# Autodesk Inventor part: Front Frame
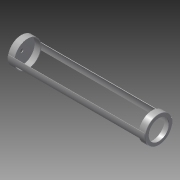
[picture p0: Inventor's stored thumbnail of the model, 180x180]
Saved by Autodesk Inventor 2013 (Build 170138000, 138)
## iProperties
Created: 2009-03
Part Number: Front Frame
Document SubType Name: Modeling
Designer: tangg
Density: 7.86 g/cm^3
Material: Steel, Mild
Mass: 173.384 g
Surface Area: 347.527 cm^2
Volume: 22.059 cm^3
Author: tangg
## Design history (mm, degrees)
sketch "Sketch1"
  geometry: L1 (-14.427, -29.5)-(-1, -29.5); L2 (0, -28.5)-(0, 0); L3 (0, 0)-(-1.5, 0); L4 (-14.427, -28)-(-14.427, -29.5); L5 (-14.427, -28)-(-1.5, -28); L6 (-1.5, -28)-(-1.5, 0); L7 (-1.5, 0)-(-17.075, 0); L8 (-150, -53.823)-(-150, 38.657); L9 (-285.573, -29.5)-(-299, -29.5); L10 (-300, -28.5)-(-300, 0); L11 (-300, 0)-(-298.5, 0); L12 (-285.573, -28)-(-285.573, -29.5); L13 (-285.573, -28)-(-298.5, -28); L14 (-298.5, -28)-(-298.5, 0); L15 (-298.5, 0)-(-282.925, 0); A1 r 1 centre (-1, -28.5) between (-1, -29.5) and (0, -28.5); A2 r 1 centre (-299, -28.5) between (-300, -28.5) and (-299, -29.5); 2 further points
  constraints: 30 end point, 7 symmetric about line, 4 point on circle, 4 point on line, 4 tangent, 3 parallel, 3 perpendicular, 2 centre point, 2 horizontal
  dimensions: "d1" = 1.5 distance between parallel lines of L2 L6; "d2" = 1.5 distance between parallel lines of L1 L5; "d3" = 150 distance from line of L8 L2.end; "d13" = 28 distance from line of L5 L3.end; "d14" = 1 radius of A1; "d15" = 1 radius of A2
revolve "Revolution1" sketch "Sketch1" stored, may be unused: angle "d0" = 90 deg
sketch "Sketch2"
  geometry: C1 r 3.525 at (0, 0); C2 r 29.5 at (0, 0) reference; C3 r 29.5 at (0, 0) reference
  constraints: 1 centre point
  dimensions: "d4" = 7.05 diameter of C1
extrude "Extrusion1" cut sketch "Sketch2" distance "d5" = 10; taper "d6" = 0 deg
sketch "Sketch3"
  geometry: C1 r 29.5 at (0, 0) reference; C2 r 22.086 at (0, 0); 1 further point
  constraints: 1 centre point
extrude "Extrusion2" cut sketch "Sketch3" distance "d8" = 10; taper "d9" = 0 deg
workplane "Work Plane1"
sketch "Sketch4"
  geometry: L1 (25.167, -7.002)-(24.114, -7.26); L2 (25.167, 7.002)-(24.114, 7.26); L3 (24.114, -7.26)-(25.167, -7.002); L4 (82.48, 7.002)-(83.533, 7.26); L5 (24.114, 7.26)-(25.167, 7.002); L6 (82.48, -7.002)-(83.533, -7.26); A1 r 30.584 centre (53.823, 0) between (24.114, 7.26) and (24.114, -7.26); A2 r 30.584 centre (53.823, 0) between (83.533, -7.26) and (83.533, 7.26); A3 r 29.5 centre (53.823, 0) between (82.48, 7.002) and (82.48, -7.002) reference; 2 further points
  constraints: 12 end point, 8 point on circle, 2 centre point, 2 coincident, 2 collinear, 3 other
extrude "Extrusion3" join sketch "Sketch4" stored distance "d11" = 298; taper "d12" = 0 deg
body "Solid1"
node "Projected Loop1"
other parameters: "d10" = 0
